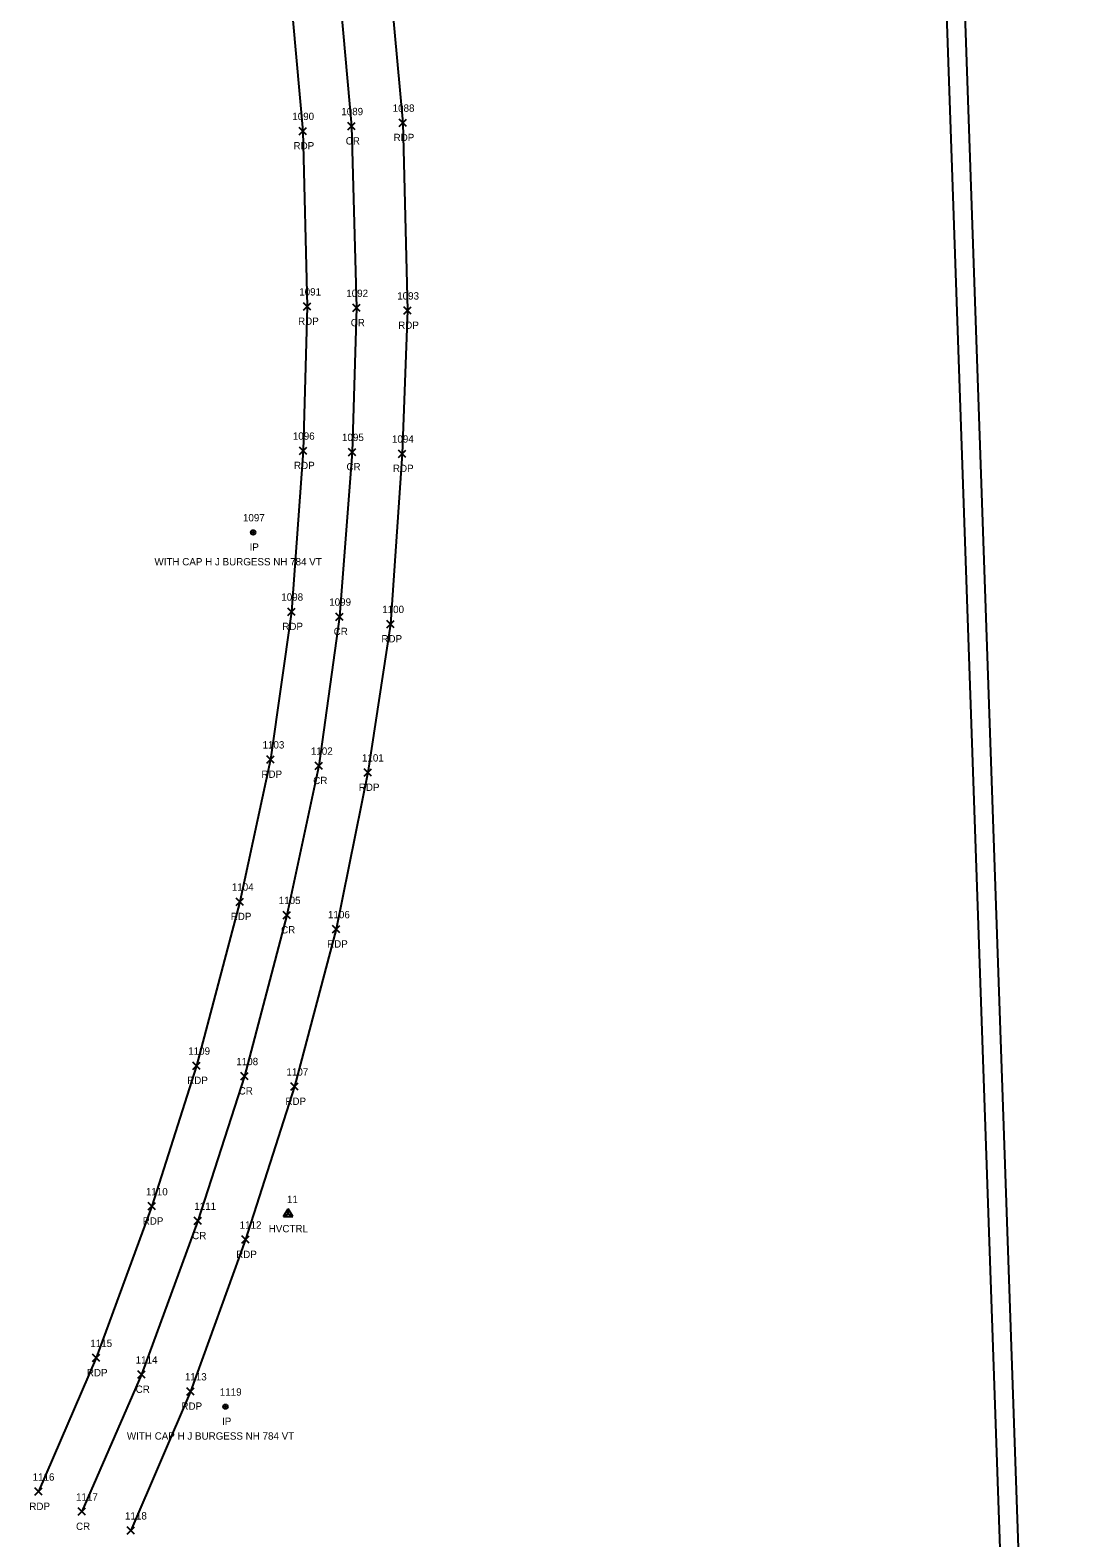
# Model space of a CAD drawing. Extents: x 1754529 to 1755810, y 621660 to 624656.
# Drawn here: x 1755364.8 to 1755653.8, y 622338.3 to 622749.4 of the extents above; entities that cross this region are included whole.
import ezdxf

# ---------------------------------------------------------------- set-up
doc = ezdxf.new("R2010")
doc.units = 0
for name, color, linetype in [('C_A', 7, 'Continuous'), ('C_I', 7, 'Continuous'), ('CPSM', 7, 'Continuous'), ('Level 14', 7, 'Continuous'), ('M_A', 7, 'Continuous'), ('M_C', 7, 'Continuous'), ('M_I', 7, 'Continuous'), ('MPIR', 7, 'Continuous'), ('P_A', 7, 'Continuous'), ('P_I', 7, 'Continuous'), ('PET', 7, 'Continuous'), ('PRC', 7, 'Continuous'), ('RR', 7, 'Continuous')]:
    doc.layers.add(name, color=color, linetype=linetype)

msp = doc.modelspace()

# ---------------------------------------------------------------- linework, layer by layer
at = {"layer": 'CPSM'}
for p, q in [((1755433.95, 622425.91), (1755435.2, 622428.08)), ((1755436.45, 622425.91), (1755435.2, 622428.08)), ((1755435.2, 622426.63), (1755435.2, 622428.08)), ((1755433.95, 622425.91), (1755435.2, 622426.63)), ((1755433.95, 622425.91), (1755436.45, 622425.91)), ((1755435.2, 622426.63), (1755435.2, 622426.63)), ((1755435.2, 622426.63), (1755436.45, 622425.91))]:
    msp.add_line(p, q, dxfattribs=at)
at = {"layer": 'Level 14'}
for points in [[(1755451.46, 622722.25), (1755453.46, 622724.25)], [(1755453.46, 622722.25), (1755451.46, 622724.25)], [(1755465.46, 622723.18), (1755467.46, 622725.18)], [(1755467.46, 622723.18), (1755465.46, 622725.18)], [(1755438.16, 622720.92), (1755440.16, 622722.92)], [(1755440.16, 622720.92), (1755438.16, 622722.92)], [(1755439.41, 622673.08), (1755441.41, 622675.08)], [(1755441.41, 622673.08), (1755439.41, 622675.08)], [(1755452.82, 622672.68), (1755454.82, 622674.68)], [(1755454.82, 622672.68), (1755452.82, 622674.68)], [(1755466.7, 622671.98), (1755468.7, 622673.98)], [(1755468.7, 622671.98), (1755466.7, 622673.98)], [(1755438.3, 622633.75), (1755440.3, 622635.75)], [(1755440.3, 622633.75), (1755438.3, 622635.75)], [(1755451.65, 622633.4), (1755453.65, 622635.4)], [(1755453.65, 622633.4), (1755451.65, 622635.4)], [(1755465.27, 622632.95), (1755467.27, 622634.95)], [(1755467.27, 622632.95), (1755465.27, 622634.95)], [(1755435.09, 622589.86), (1755437.09, 622591.86)], [(1755437.09, 622589.86), (1755435.09, 622591.86)], [(1755448.17, 622588.49), (1755450.17, 622590.49)], [(1755450.17, 622588.49), (1755448.17, 622590.49)], [(1755462.13, 622586.49), (1755464.13, 622588.49)], [(1755464.13, 622586.49), (1755462.13, 622588.49)], [(1755429.4, 622549.56), (1755431.4, 622551.56)], [(1755431.4, 622549.56), (1755429.4, 622551.56)], [(1755442.6, 622547.85), (1755444.6, 622549.85)], [(1755444.6, 622547.85), (1755442.6, 622549.85)], [(1755455.96, 622546), (1755457.96, 622548)], [(1755457.96, 622546), (1755455.96, 622548)], [(1755421.04, 622510.78), (1755423.04, 622512.78)], [(1755423.04, 622510.78), (1755421.04, 622512.78)], [(1755433.83, 622507.14), (1755435.83, 622509.14)], [(1755435.83, 622507.14), (1755433.83, 622509.14)], [(1755447.32, 622503.27), (1755449.32, 622505.27)], [(1755449.32, 622503.27), (1755447.32, 622505.27)], [(1755409.15, 622466.07), (1755411.15, 622468.07)], [(1755411.15, 622466.07), (1755409.15, 622468.07)], [(1755422.27, 622463.21), (1755424.27, 622465.21)], [(1755424.27, 622463.21), (1755422.27, 622465.21)], [(1755435.94, 622460.37), (1755437.94, 622462.37)], [(1755437.94, 622460.37), (1755435.94, 622462.37)], [(1755397.03, 622427.72), (1755399.03, 622429.72)], [(1755399.03, 622427.72), (1755397.03, 622429.72)], [(1755409.58, 622423.75), (1755411.58, 622425.75)], [(1755411.58, 622423.75), (1755409.58, 622425.75)], [(1755422.52, 622418.63), (1755424.52, 622420.63)], [(1755424.52, 622418.63), (1755422.52, 622420.63)], [(1755381.8, 622386.37), (1755383.8, 622388.37)], [(1755383.8, 622386.37), (1755381.8, 622388.37)], [(1755394.16, 622381.85), (1755396.16, 622383.85)], [(1755396.16, 622381.85), (1755394.16, 622383.85)], [(1755407.59, 622377.24), (1755409.59, 622379.24)], [(1755409.59, 622377.24), (1755407.59, 622379.24)], [(1755366.12, 622349.92), (1755368.12, 622351.92)], [(1755368.12, 622349.92), (1755366.12, 622351.92)], [(1755377.9, 622344.47), (1755379.9, 622346.47)], [(1755379.9, 622344.47), (1755377.9, 622346.47)], [(1755391.26, 622339.32), (1755393.26, 622341.32)], [(1755393.26, 622339.32), (1755391.26, 622341.32)]]:
    msp.add_lwpolyline(points, dxfattribs=at)
at = {"layer": 'MPIR'}
for centre, radius in [((1755425.64, 622612.49), 0.625), ((1755425.64, 622612.49), 0.0833), ((1755418.11, 622374.1), 0.625), ((1755418.11, 622374.1), 0.0833)]:
    msp.add_circle(centre, radius, dxfattribs=at)
at = {"layer": 'PET'}
for points in [[(1755375.95, 623174.43), (1755377.19, 623132.58), (1755381.06, 623081.36), (1755385.46, 623042.22), (1755391.35, 623004.09), (1755398.98, 622961.77), (1755409.52, 622911.02), (1755418.82, 622867.94), (1755427.14, 622823.84), (1755434.61, 622772.46), (1755439.16, 622721.92), (1755440.41, 622674.08), (1755439.3, 622634.75), (1755436.09, 622590.86), (1755430.4, 622550.56), (1755422.04, 622511.78), (1755410.15, 622467.07), (1755398.03, 622428.72), (1755382.8, 622387.37), (1755367.12, 622350.92)], [(1755461.87, 622774.73), (1755466.46, 622724.18), (1755467.7, 622672.98), (1755466.27, 622633.95), (1755463.13, 622587.49), (1755456.96, 622547), (1755448.32, 622504.27), (1755436.94, 622461.37), (1755423.52, 622419.63), (1755408.59, 622378.24), (1755392.26, 622340.32)]]:
    msp.add_lwpolyline(points, dxfattribs=at)
at = {"layer": 'PRC'}
msp.add_lwpolyline([(1755389.28, 623175.01), (1755390.29, 623132.74), (1755394.1, 623083.18), (1755398.56, 623044.45), (1755404.15, 623007.45), (1755412.15, 622963.41), (1755422.77, 622912.86), (1755431.8, 622870.62), (1755439.96, 622826.95), (1755447.94, 622774.03), (1755452.46, 622723.25), (1755453.82, 622673.68), (1755452.65, 622634.4), (1755449.17, 622589.49), (1755443.6, 622548.85), (1755434.83, 622508.14), (1755423.27, 622464.21), (1755410.58, 622424.75), (1755395.16, 622382.85), (1755378.9, 622345.47)], dxfattribs=at)
at = {"layer": 'RR'}
for points in [[(1755648.95, 621764.81), (1755636.45, 622131.43), (1755613.67, 622787.88), (1755609.16, 622923.97), (1755607.65, 622970.2), (1755606.39, 623016.18), (1755605.63, 623052.66), (1755604.97, 623087.09), (1755604.49, 623127.28), (1755604.22, 623170.71)], [(1755653.84, 621764.86), (1755641.42, 622131.55), (1755638.13, 622228.47), (1755618.69, 622787.98), (1755614.09, 622923.65), (1755612.57, 622970.4), (1755611.33, 623016.44), (1755610.51, 623052.88), (1755609.89, 623087.03), (1755609.4, 623127.16), (1755609.16, 623170.67)]]:
    msp.add_lwpolyline(points, dxfattribs=at)

# ---------------------------------------------------------------- texts
at = {"layer": 'C_A'}
msp.add_text('HVCTRL', height=2, dxfattribs=at).set_placement((1755429.9, 622421.63))
at = {"layer": 'C_I'}
msp.add_text('11', height=2, dxfattribs=at).set_placement((1755434.87, 622429.63))
at = {"layer": 'M_A'}
for p in [(1755424.68, 622607.49), (1755417.16, 622369.1)]:
    msp.add_text('IP', height=2, dxfattribs=at).set_placement(p)
at = {"layer": 'M_C'}
for p in [(1755398.73, 622603.49), (1755391.21, 622365.1)]:
    msp.add_text('WITH CAP H J BURGESS NH 784 VT', height=2, dxfattribs=at).set_placement(p)
at = {"layer": 'M_I'}
for s, p in [('1097', (1755422.86, 622615.49)), ('1119', (1755416.55, 622377.1))]:
    msp.add_text(s, height=2, dxfattribs=at).set_placement(p)
at = {"layer": 'P_A'}
for s, p in [('CR', (1755450.89, 622718.25)), ('RDP', (1755463.95, 622719.18)), ('RDP', (1755436.65, 622716.92)), ('RDP', (1755437.9, 622669.08)), ('CR', (1755452.25, 622668.68)), ('RDP', (1755465.19, 622667.98)), ('RDP', (1755436.79, 622629.75)), ('CR', (1755451.09, 622629.4)), ('RDP', (1755463.76, 622628.95)), ('RDP', (1755433.58, 622585.86)), ('CR', (1755447.6, 622584.49)), ('RDP', (1755460.62, 622582.49)), ('RDP', (1755427.89, 622545.56)), ('CR', (1755442.03, 622543.85)), ('RDP', (1755454.45, 622542)), ('RDP', (1755419.52, 622506.78)), ('CR', (1755433.26, 622503.14)), ('RDP', (1755445.8, 622499.27)), ('RDP', (1755407.64, 622462.07)), ('CR', (1755421.7, 622459.21)), ('RDP', (1755434.43, 622456.37)), ('RDP', (1755395.52, 622423.72)), ('CR', (1755409.01, 622419.75)), ('RDP', (1755421, 622414.63)), ('RDP', (1755380.29, 622382.37)), ('CR', (1755393.6, 622377.85)), ('RDP', (1755406.08, 622373.24)), ('RDP', (1755364.6, 622345.92)), ('CR', (1755377.33, 622340.47))]:
    msp.add_text(s, height=2, dxfattribs=at).set_placement(p)
at = {"layer": 'P_I'}
for s, p in [('1089', (1755449.68, 622726.25)), ('1088', (1755463.69, 622727.18)), ('1090', (1755436.31, 622724.92)), ('1091', (1755438.21, 622677.08)), ('1092', (1755451.04, 622676.68)), ('1093', (1755464.93, 622675.98)), ('1096', (1755436.47, 622637.75)), ('1095', (1755449.88, 622637.4)), ('1094', (1755463.5, 622636.95)), ('1098', (1755433.32, 622593.86)), ('1099', (1755446.39, 622592.49)), ('1100', (1755460.84, 622590.49)), ('1103', (1755428.2, 622553.56)), ('1102', (1755441.39, 622551.85)), ('1101', (1755455.32, 622550)), ('1104', (1755419.83, 622514.78)), ('1105', (1755432.62, 622511.14)), ('1106', (1755446.06, 622507.27)), ('1109', (1755407.94, 622470.07)), ('1108', (1755421.06, 622467.21)), ('1107', (1755434.73, 622464.37)), ('1110', (1755396.39, 622431.72)), ('1111', (1755409.59, 622427.75)), ('1112', (1755421.96, 622422.63)), ('1115', (1755381.24, 622390.37)), ('1114', (1755393.61, 622385.85)), ('1113', (1755407.03, 622381.24)), ('1116', (1755365.5, 622353.92)), ('1117', (1755377.34, 622348.47)), ('1118', (1755390.7, 622343.32))]:
    msp.add_text(s, height=2, dxfattribs=at).set_placement(p)

doc.saveas('drawing.dxf')
